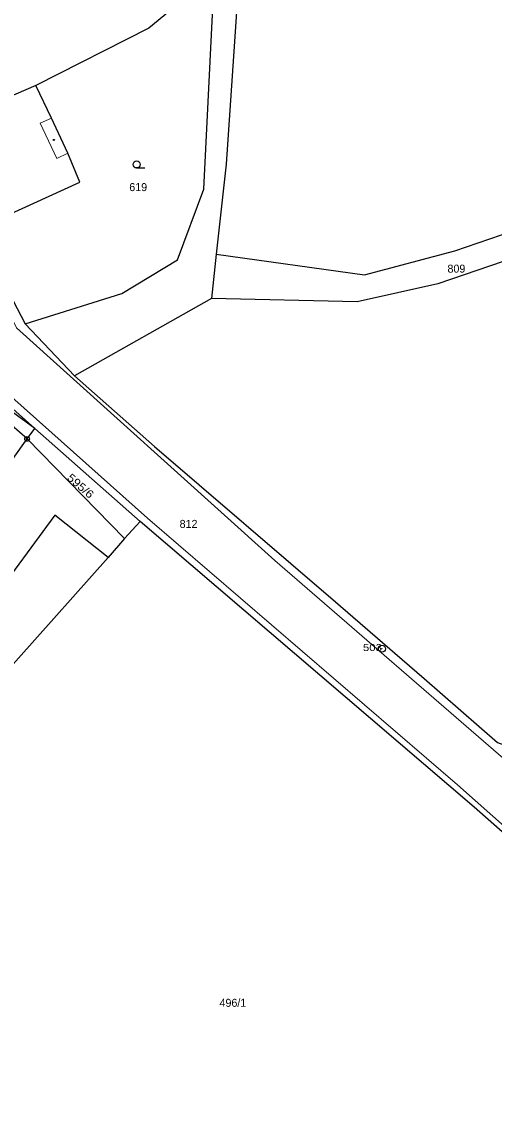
# Model space of a CAD drawing. Extents: x -687135 to -684370, y -1007309 to -1005782.
# Drawn here: x -685021.3 to -684920.8, y -1006674.4 to -1006444.6 of the extents above; entities that cross this region are included whole.
import ezdxf
from ezdxf.enums import TextEntityAlignment as Align

# ---------------------------------------------------------------- set-up
doc = ezdxf.new("R2010")
doc.units = 0
doc.header["$LTSCALE"] = 0.68
for name, color, linetype, lineweight in [('1', 7, 'Continuous', 25), ('3', 7, 'Continuous', 25), ('4', 7, 'Continuous', 13), ('5', 7, 'Continuous', 25), ('8', 7, 'Continuous', 25)]:
    doc.layers.add(name, color=color, linetype=linetype, lineweight=lineweight)
doc.layers.add('2', color=7, linetype='Continuous')

msp = doc.modelspace()

# ---------------------------------------------------------------- linework, layer by layer
at = {"layer": '1'}
for p, q in [((-685031.08, -1006488.72), (-685020.6, -1006508.76)), ((-684979.92, -1006493.97), (-684980.95, -1006503.36)), ((-685020.6, -1006508.76), (-685010.09, -1006519.79)), ((-685018.5, -1006531), (-684996.13, -1006550.77)), ((-685044.3, -1006567.02), (-685020.17, -1006533.22))]:
    msp.add_line(p, q, dxfattribs=at)
for points in [[(-684900.57, -1006302.99), (-684907.23, -1006311.42), (-684918.18, -1006325.47), (-684932.07, -1006347.35), (-684944, -1006366.68), (-684955.53, -1006384.87), (-684969.03, -1006410.25), (-684975.28, -1006437.24), (-684977.83, -1006474.8), (-684979.92, -1006493.97)], [(-685020.6, -1006508.76), (-685000.01, -1006502.31), (-684988.15, -1006495.16), (-684982.57, -1006480.15), (-684980.32, -1006434.42)], [(-684980.32, -1006434.42), (-684994.25, -1006445.97), (-685018.29, -1006458.13)], [(-685018.29, -1006458.13), (-685040.8, -1006467.83), (-685031.08, -1006488.72)], [(-685031.08, -1006488.72), (-685008.96, -1006478.66), (-685011.5, -1006472.51), (-685014.97, -1006465.08), (-685018.29, -1006458.13)], [(-684979.92, -1006493.97), (-684948.43, -1006498.37), (-684929.18, -1006493.22), (-684906.88, -1006485.6), (-684882.68, -1006473.01)], [(-684877.48, -1006481.32), (-684932.8, -1006500.28), (-684949.95, -1006504.09), (-684980.95, -1006503.36), (-685010.09, -1006519.79)], [(-685018.5, -1006531), (-685027.04, -1006524.82), (-685028.47, -1006523.43), (-685031.56, -1006520.39)], [(-685029.1, -1006519.47), (-685025.2, -1006525.08), (-685018.5, -1006531)], [(-685010.09, -1006519.79), (-684993.05, -1006534.8), (-684954.59, -1006567.81), (-684941.96, -1006578.76), (-684935.76, -1006584.14), (-684920.1, -1006597.74), (-684868.88, -1006616.37), (-684824.1, -1006544.38)], [(-685020.17, -1006533.22), (-685029.97, -1006524.71), (-685042.37, -1006524.46), (-685058.8, -1006530.22)], [(-684999.43, -1006554.36), (-685020.17, -1006533.22), (-685018.5, -1006531)], [(-684996.13, -1006550.77), (-684999.43, -1006554.36), (-685002.92, -1006558.42), (-685041.12, -1006601.16), (-685045.06, -1006605.58), (-685083.94, -1006649.24), (-685059.06, -1006657.45)], [(-685002.92, -1006558.42), (-685014.29, -1006549.41), (-685041.44, -1006586.25)], [(-684841, -1006685.58), (-684847.2, -1006680.11), (-684925.08, -1006611.45), (-684996.13, -1006550.77)]]:
    msp.add_lwpolyline(points, dxfattribs=at)
at = {"layer": '3'}
msp.add_line((-684996.863, -1006475.64), (-684995.113, -1006475.64), dxfattribs=at)
msp.add_circle((-684996.8629, -1006474.8898), 0.75, dxfattribs=at)
at = {"layer": '4'}
for p, q in [((-685014.97, -1006465.08), (-685017.36, -1006466.12)), ((-685013.86, -1006473.61), (-685017.36, -1006466.12)), ((-685011.5, -1006472.51), (-685013.86, -1006473.61)), ((-685026.12, -1006521.97), (-684994.58, -1006550.04))]:
    msp.add_line(p, q, dxfattribs=at)
for points in [[(-685065.37, -1006416.52), (-685042.68, -1006466.37), (-685032.4, -1006488.74), (-685022.44, -1006509.59), (-684967.45, -1006559.07), (-684916.25, -1006603.35), (-684856.74, -1006654.98), (-684782.53, -1006719.91)], [(-684814.07, -1006708.45), (-684837.78, -1006687.33), (-684853.52, -1006673.26), (-684928.63, -1006606.71), (-684994.58, -1006550.04)]]:
    msp.add_lwpolyline(points, dxfattribs=at)
at = {"layer": '5'}
msp.add_circle((-685014.4748, -1006469.6894), 0.1225, dxfattribs=at)
at = {"layer": '8'}
for centre, radius in [((-685020.17, -1006533.2199), 0.5), ((-685020.17, -1006533.2199), 0.0303), ((-684944.72, -1006577.7898), 0.75), ((-684944.72, -1006577.7898), 0.03)]:
    msp.add_circle(centre, radius, dxfattribs=at)

# ---------------------------------------------------------------- texts
at = {"layer": '2'}
for s, p in [('619', (-684998.43, -1006480.559)), ('809', (-684930.77, -1006497.88)), ('812', (-684987.72, -1006552.12)), ('496/1', (-684979.24, -1006653.87))]:
    msp.add_text(s, height=1.7, dxfattribs=at).set_placement(p)
at = {"layer": '2', "width": 1.15}
msp.add_text('595/6', height=1.7, rotation=319, dxfattribs=at).set_placement((-685011.817, -1006541.701))
at = {"layer": '8', "width": 1.2}
msp.add_text('503', height=1.5, dxfattribs=at).set_placement((-684944.72, -1006578.29), align=Align.RIGHT)

doc.saveas('drawing.dxf')
